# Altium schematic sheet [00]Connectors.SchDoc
size A4; SheetNumber: 5; SheetTotal: 5
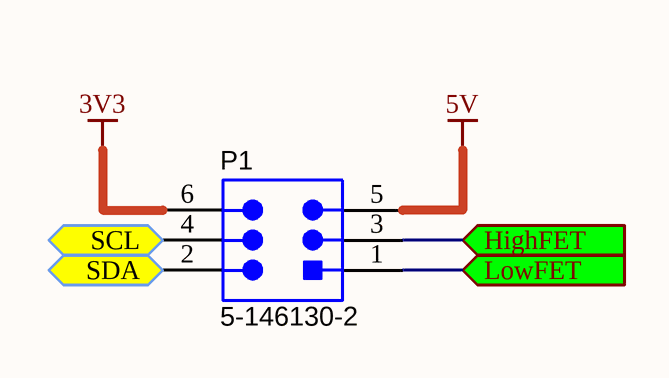
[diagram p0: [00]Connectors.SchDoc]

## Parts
P1  5-146130-2  [TECO-5-146130-2_V]

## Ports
HighFET (in, see [05]BuckConverter[1B], [05]BuckConverter[1C]), LowFET (in, see [05]BuckConverter[1B], [05]BuckConverter[1C]), SCL (bidir, see [06]TemperatureSense[2C], [06]TemperatureSense[4C]), SDA (bidir, see [06]TemperatureSense[2B], [06]TemperatureSense[4C])

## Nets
3V3: P1.6
5V: P1.5
HighFET: P1.3 ; port HighFET
LowFET: P1.1 ; port LowFET
SCL: P1.4 ; port SCL
SDA: P1.2 ; port SDA

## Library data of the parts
P1 = CMP-002-00018-2: Male Header, Pitch 2.54 mm, 2 x 3 Position, Height 8.13 mm, -65 to 125 degC, RoHS, Tube; Manufacturer: TE Connectivity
